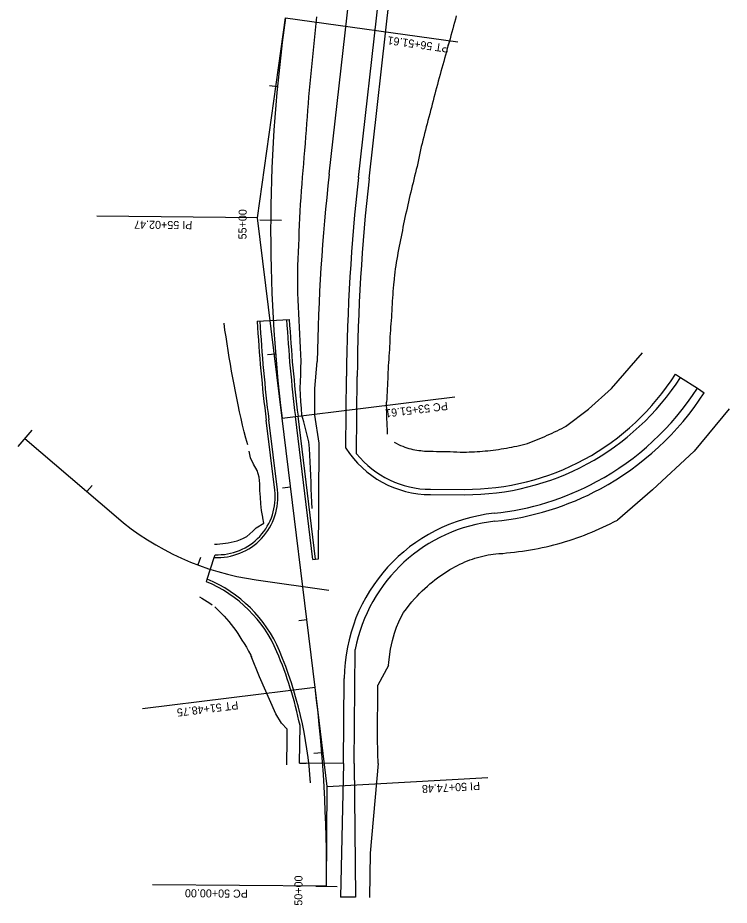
# Model space of a CAD drawing. Extents: x 1304554 to 1314558, y 2088110 to 2090513.
# Drawn here: x 1313759 to 1314290, y 2088110 to 2088773 of the extents above; entities that cross this region are included whole.
import ezdxf

# ---------------------------------------------------------------- set-up
doc = ezdxf.new("R2010")
doc.units = 0
for name, color, linetype in [('R_Horz Alg', 7, 'Continuous'), ('R_Horz Alg Annot', 7, 'Continuous'), ('R_Horz Alg Stationing', 7, 'Continuous'), ('R_Horz Alg Stationing_Detour', 7, 'Continuous'), ('R_Proposed Const Limits', 7, 'Continuous'), ('R_Proposed Road', 7, 'Continuous'), ('R_Shoulder', 7, 'Continuous')]:
    doc.layers.add(name, color=color, linetype=linetype)

msp = doc.modelspace()

# ---------------------------------------------------------------- linework, layer by layer
at = {"layer": 'R_Horz Alg'}
for p, q in [((1313980.75, 2088272.19), (1313956.03, 2088473.54)), ((1313980.75, 2088272.19), (1313956.03, 2088473.54)), ((1313980.75, 2088272.19), (1313956.03, 2088473.54)), ((1313763.74, 2088458.44), (1313831.96, 2088400)), ((1313936.6, 2088352.77), (1313990.95, 2088345.13))]:
    msp.add_line(p, q, dxfattribs=at)
for centre, radius, start, end in [((1315093.4, 2088613.19), 1145.92, 172, 187), ((1315093.4, 2088613.19), 1145.92, 172, 187), ((1313965.08, 2088555.41), 204.63, 229.41667, 262), ((1312843.38, 2088132.54), 1145.92, 359.5625, 7), ((1312843.38, 2088132.54), 1145.92, 359.5625, 7)]:
    msp.add_arc(centre, radius, start, end, dxfattribs=at)
at = {"layer": 'R_Horz Alg Annot'}
for points in [[(1313956.03, 2088473.54), (1313937.64, 2088623.28), (1313958.64, 2088772.67)], [(1313958.64, 2088772.67), (1314087.38, 2088754.58)], [(1313937.64, 2088623.28), (1313817.65, 2088624.33)], [(1313956.03, 2088473.54), (1314085.06, 2088489.38)], [(1313980.75, 2088272.19), (1313851.72, 2088256.35)], [(1313989.26, 2088123.79), (1313989.83, 2088198.27), (1313980.75, 2088272.19)], [(1313989.83, 2088198.27), (1314109.63, 2088205.14)], [(1313989.26, 2088123.79), (1313859.26, 2088124.78)]]:
    msp.add_lwpolyline(points, dxfattribs=at)
at = {"layer": 'R_Horz Alg Stationing'}
for points in [[(1313946.64, 2088721.99), (1313952.61, 2088721.42)], [(1313939.52, 2088621.64), (1313955.52, 2088621.52)], [(1313945.17, 2088521.2), (1313951.15, 2088521.68)], [(1313956.36, 2088421.58), (1313962.32, 2088422.31)], [(1313968.55, 2088322.33), (1313974.51, 2088323.06)], [(1313968.55, 2088322.33), (1313974.51, 2088323.06)], [(1313979.68, 2088223.22), (1313985.66, 2088223.69)], [(1313981.26, 2088123.85), (1313997.26, 2088123.73)]]:
    msp.add_lwpolyline(points, dxfattribs=at)
at = {"layer": 'R_Horz Alg Stationing_Detour'}
for points in [[(1313768.94, 2088464.52), (1313758.53, 2088452.37)], [(1313814.03, 2088423.26), (1313810.13, 2088418.71)], [(1313895.09, 2088369.52), (1313892.97, 2088363.91)]]:
    msp.add_lwpolyline(points, dxfattribs=at)
at = {"layer": 'R_Proposed Const Limits'}
msp.add_line((1314035.5, 2088288.69), (1314027.56, 2088274.13), dxfattribs=at)
for points in [[(1314086.21, 2088774.06), (1314085.54, 2088771.62), (1314084.86, 2088769.18), (1314084.19, 2088766.74), (1314083.52, 2088764.3), (1314082.84, 2088761.87), (1314082.16, 2088759.43), (1314081.49, 2088756.99), (1314080.81, 2088754.55), (1314080.14, 2088752.11), (1314079.46, 2088749.67), (1314078.79, 2088747.23), (1314078.11, 2088744.79), (1314077.43, 2088742.35), (1314076.76, 2088739.91), (1314076.08, 2088737.47), (1314075.41, 2088735.03), (1314074.73, 2088732.59), (1314074.03, 2088730.15), (1314073.33, 2088727.72), (1314072.69, 2088725.27), (1314072.04, 2088722.83), (1314071.4, 2088720.39), (1314070.75, 2088717.94), (1314070.12, 2088715.5), (1314069.48, 2088713.06), (1314068.85, 2088710.61), (1314068.22, 2088708.17), (1314067.58, 2088705.72), (1314066.95, 2088703.28), (1314066.31, 2088700.83), (1314065.68, 2088698.39), (1314065.04, 2088695.95), (1314064.41, 2088693.5), (1314063.77, 2088691.06), (1314063.14, 2088688.61), (1314062.51, 2088686.17), (1314061.87, 2088683.72), (1314061.24, 2088681.28), (1314060.6, 2088678.84), (1314060.05, 2088676.38), (1314059.55, 2088673.92), (1314059.05, 2088671.46), (1314058.55, 2088669), (1314058.05, 2088666.54), (1314057.5, 2088664.09), (1314056.87, 2088661.65), (1314056.24, 2088659.2), (1314055.62, 2088656.75), (1314055.04, 2088654.3), (1314054.45, 2088651.85), (1314053.87, 2088649.4), (1314053.3, 2088647.02), (1314052.74, 2088644.66), (1314052.18, 2088642.29), (1314051.59, 2088639.93), (1314051.01, 2088637.57), (1314050.45, 2088635.21), (1314049.92, 2088632.84), (1314049.4, 2088630.47), (1314048.88, 2088628.09), (1314048.36, 2088625.72), (1314047.86, 2088623.34), (1314047.35, 2088620.97), (1314046.86, 2088618.59), (1314046.36, 2088616.21), (1314045.88, 2088613.83), (1314045.4, 2088611.44), (1314044.92, 2088609.06), (1314044.45, 2088606.67), (1314043.99, 2088604.28), (1314043.53, 2088601.9), (1314043.08, 2088599.51), (1314042.63, 2088597.11), (1314042.22, 2088594.72), (1314041.78, 2088592.33), (1314041.34, 2088589.93), (1314040.9, 2088587.53), (1314040.58, 2088585.13), (1314040.31, 2088582.72), (1314040.04, 2088580.31), (1314039.78, 2088577.9), (1314039.7, 2088577.16), (1314039.54, 2088575.49), (1314039.31, 2088573.08), (1314039.09, 2088570.67), (1314038.87, 2088568.25), (1314038.68, 2088565.84), (1314038.52, 2088563.42), (1314038.37, 2088561), (1314038.22, 2088558.59), (1314038.08, 2088556.17), (1314037.94, 2088553.75), (1314037.8, 2088551.33), (1314037.67, 2088548.91), (1314037.49, 2088546.49), (1314037.3, 2088544.08), (1314037.12, 2088541.66), (1314036.94, 2088539.24), (1314036.76, 2088536.82), (1314036.64, 2088534.4), (1314036.52, 2088531.98), (1314036.41, 2088529.56), (1314036.31, 2088527.14), (1314036.18, 2088524.72), (1314036.02, 2088522.29), (1314035.86, 2088519.87), (1314035.71, 2088517.45), (1314035.56, 2088515.03), (1314035.41, 2088512.61), (1314035.27, 2088510.18), (1314035.15, 2088507.76), (1314035.07, 2088505.33), (1314035, 2088502.86), (1314034.87, 2088500.36), (1314034.73, 2088497.86), (1314034.6, 2088495.36), (1314034.46, 2088492.86), (1314034.33, 2088490.36), (1314034.2, 2088487.86), (1314034.07, 2088485.36)], [(1313978.43, 2088406.02), (1313978.26, 2088410.79), (1313978.07, 2088415.79), (1313977.88, 2088420.79), (1313977.68, 2088425.79), (1313977.46, 2088430.8), (1313977.22, 2088435.8), (1313976.97, 2088440.8), (1313976.74, 2088445.8), (1313976.52, 2088450.8), (1313976.1, 2088455.81), (1313974.82, 2088460.82), (1313973.59, 2088465.83), (1313972.34, 2088470.84), (1313970.83, 2088475.85), (1313970.48, 2088480.85), (1313970.14, 2088485.85), (1313969.8, 2088490.86), (1313969.45, 2088495.86), (1313969.69, 2088500.86), (1313969.93, 2088505.87), (1313970.16, 2088510.94), (1313970.4, 2088516.02), (1313970.09, 2088521.1), (1313969.8, 2088526.18), (1313969.53, 2088531.27), (1313969.24, 2088536.36), (1313968.97, 2088541.46), (1313968.71, 2088546.55), (1313968.47, 2088551.65), (1313968.25, 2088556.75), (1313968.06, 2088561.86), (1313967.89, 2088566.96), (1313967.74, 2088572.07), (1313967.69, 2088577.17), (1313967.68, 2088582.27), (1313967.84, 2088587.37), (1313968.01, 2088592.46), (1313968.21, 2088597.56), (1313968.44, 2088602.65), (1313968.67, 2088607.75), (1313968.9, 2088612.84), (1313969.12, 2088617.94), (1313969.35, 2088623.04), (1313969.6, 2088628.14), (1313969.87, 2088633.23), (1313970.19, 2088638.33), (1313970.57, 2088643.42), (1313970.97, 2088648.5), (1313971.38, 2088653.59), (1313971.81, 2088658.66), (1313972.23, 2088663.65), (1313972.65, 2088668.63), (1313973.08, 2088673.61), (1313973.46, 2088678.6), (1313973.84, 2088683.59), (1313974.2, 2088688.58), (1313974.58, 2088693.57), (1313974.96, 2088698.56), (1313975.33, 2088703.55), (1313975.7, 2088708.54), (1313976.07, 2088713.53), (1313976.51, 2088718.51), (1313976.99, 2088723.49), (1313977.48, 2088728.47), (1313977.96, 2088733.45), (1313978.44, 2088738.42), (1313978.93, 2088743.4), (1313979.41, 2088748.38), (1313979.89, 2088753.35), (1313980.38, 2088758.33), (1313980.88, 2088763.31), (1313981.46, 2088768.27), (1313982.06, 2088773.24)], [(1313930.55, 2088453.68), (1313928.84, 2088458.5), (1313927.63, 2088463.39), (1313926.75, 2088467.2), (1313926.5, 2088468.29), (1313925.37, 2088473.28), (1313924.24, 2088478.32), (1313923.14, 2088483.36), (1313922.12, 2088488.42), (1313921.13, 2088493.49), (1313920.16, 2088498.56), (1313919.2, 2088503.63), (1313918.28, 2088508.72), (1313917.39, 2088513.81), (1313916.5, 2088518.9), (1313915.66, 2088524.01), (1313914.92, 2088529.12), (1313914.15, 2088534.23), (1313913.37, 2088539.35), (1313912.69, 2088544.48)], [(1314167.68, 2088467.3), (1314185.05, 2088480.27), (1314202.04, 2088495.78), (1314225.41, 2088522.31)], [(1314034.89, 2088461.56), (1314034.8, 2088462.86), (1314034.69, 2088465.36), (1314034.58, 2088467.86), (1314034.47, 2088470.36), (1314034.36, 2088472.86), (1314034.28, 2088475.36), (1314034.27, 2088477.86), (1314034.24, 2088480.36), (1314034.12, 2088482.86), (1314034.07, 2088485.36)], [(1314290.13, 2088480.41), (1314264.03, 2088448.82), (1314232.76, 2088419.88), (1314206.53, 2088397.34)], [(1314039.74, 2088455.67), (1314041.35, 2088454.73), (1314042.97, 2088453.93), (1314044.56, 2088453.2), (1314046.13, 2088452.55), (1314047.69, 2088451.97), (1314049.22, 2088451.45), (1314050.74, 2088450.98), (1314052.25, 2088450.58), (1314053.74, 2088450.23), (1314055.23, 2088449.93), (1314056.7, 2088449.69), (1314058.15, 2088449.45), (1314059.59, 2088449.26), (1314061.03, 2088449.12), (1314062.46, 2088448.98), (1314063.88, 2088448.88), (1314065.3, 2088448.81), (1314066.72, 2088448.8), (1314069.02, 2088448.76), (1314071.52, 2088448.7), (1314074.02, 2088448.64), (1314076.52, 2088448.67), (1314079.02, 2088448.59), (1314081.52, 2088448.5), (1314084.02, 2088448.41), (1314086.52, 2088448.32), (1314089.02, 2088448.22), (1314091.52, 2088448.16), (1314093.74, 2088448.19), (1314095.74, 2088448.25), (1314097.75, 2088448.33), (1314099.75, 2088448.42), (1314101.75, 2088448.53), (1314103.75, 2088448.67), (1314105.75, 2088448.82), (1314107.75, 2088448.99), (1314109.74, 2088449.18), (1314111.74, 2088449.39), (1314113.73, 2088449.63), (1314115.71, 2088449.92), (1314117.7, 2088450.22), (1314119.68, 2088450.54), (1314121.66, 2088450.85), (1314123.63, 2088451.19), (1314125.61, 2088451.54), (1314127.58, 2088451.91), (1314129.55, 2088452.3), (1314131.52, 2088452.71), (1314133.49, 2088453.13), (1314135.45, 2088453.58), (1314137.4, 2088454.07), (1314139.31, 2088454.7), (1314141.2, 2088455.38), (1314143.08, 2088456.09), (1314144.96, 2088456.81), (1314146.82, 2088457.56), (1314148.68, 2088458.32), (1314150.53, 2088459.09), (1314152.37, 2088459.89), (1314154.2, 2088460.7), (1314156.02, 2088461.54), (1314157.85, 2088462.36), (1314159.67, 2088463.2), (1314161.48, 2088464.05), (1314163.27, 2088464.94), (1314165.04, 2088465.87), (1314166.81, 2088466.82), (1314168.56, 2088467.78)], [(1313938.89, 2088429.51), (1313937.35, 2088434.36), (1313934.56, 2088439.06), (1313932.4, 2088443.83), (1313931.47, 2088448.75)], [(1313942.43, 2088395.18), (1313941.7, 2088399.07), (1313941.6, 2088399.62), (1313940.69, 2088404.55), (1313940.1, 2088409.51), (1313939.79, 2088414.51), (1313939.48, 2088419.51), (1313939.31, 2088424.53), (1313938.89, 2088429.51)], [(1314046.85, 2088328.27), (1314048.89, 2088331.11), (1314050.91, 2088333.74), (1314052.91, 2088336.18), (1314054.88, 2088338.47), (1314056.85, 2088340.6), (1314058.81, 2088342.61), (1314060.74, 2088344.52), (1314062.66, 2088346.33), (1314064.57, 2088348.05), (1314066.46, 2088349.68), (1314068.35, 2088351.24), (1314070.23, 2088352.73), (1314072.09, 2088354.16), (1314073.96, 2088355.52), (1314075.83, 2088356.82), (1314077.69, 2088358.06), (1314079.55, 2088359.24), (1314081.41, 2088360.37), (1314083.28, 2088361.44), (1314085.14, 2088362.46), (1314087.01, 2088363.43), (1314088.87, 2088364.35), (1314090.74, 2088365.24), (1314092.61, 2088366.07), (1314094.48, 2088366.85), (1314096.36, 2088367.57), (1314098.24, 2088368.25), (1314100.13, 2088368.88), (1314102.07, 2088369.48), (1314104.05, 2088370.03), (1314106.02, 2088370.53), (1314107.98, 2088370.98), (1314109.94, 2088371.36), (1314111.9, 2088371.68), (1314113.86, 2088371.94), (1314115.82, 2088372.15), (1314117.88, 2088372.31), (1314120.85, 2088372.53), (1314123.82, 2088372.8), (1314126.78, 2088373.11), (1314129.74, 2088373.46), (1314132.7, 2088373.82), (1314135.66, 2088374.23), (1314138.61, 2088374.67), (1314141.56, 2088375.15), (1314144.5, 2088375.69), (1314147.43, 2088376.25), (1314150.37, 2088376.84), (1314153.29, 2088377.47), (1314156.21, 2088378.14), (1314159.12, 2088378.85), (1314162.01, 2088379.64), (1314164.88, 2088380.47), (1314167.75, 2088381.33), (1314170.61, 2088382.24), (1314173.46, 2088383.17), (1314176.29, 2088384.15), (1314179.12, 2088385.16), (1314181.92, 2088386.21), (1314184.72, 2088387.3), (1314187.5, 2088388.42), (1314190.27, 2088389.58), (1314193.02, 2088390.78), (1314195.75, 2088392.02), (1314198.47, 2088393.3), (1314201.17, 2088394.61), (1314203.86, 2088395.95), (1314206.53, 2088397.34)], [(1313905.58, 2088379.49), (1313907.58, 2088379.5), (1313909.6, 2088379.59), (1313911.65, 2088379.76), (1313913.73, 2088380.02), (1313915.85, 2088380.36), (1313918.04, 2088380.77), (1313920.27, 2088381.29), (1313922.55, 2088381.98), (1313924.88, 2088382.84), (1313927.29, 2088383.86), (1313929.68, 2088385.22), (1313931.92, 2088387.07), (1313934.24, 2088389.15), (1313936.68, 2088391.59), (1313942.43, 2088395.18)], [(1313894.21, 2088340.03), (1313896.18, 2088338.95), (1313898.14, 2088337.82), (1313900.07, 2088336.61), (1313901.99, 2088335.35), (1313903.89, 2088334.01)], [(1313905.7, 2088332.47), (1313907.49, 2088330.86), (1313909.25, 2088329.15), (1313911, 2088327.36), (1313912.77, 2088325.52), (1313914.53, 2088323.58), (1313916.3, 2088321.54), (1313918.07, 2088319.38), (1313919.84, 2088317.07), (1313921.41, 2088314.86), (1313922.95, 2088312.56), (1313924.47, 2088310.15), (1313925.98, 2088307.63), (1313927.68, 2088305.1), (1313929.37, 2088302.4), (1313931.04, 2088299.5), (1313932.7, 2088296.34), (1313933.28, 2088295.16)], [(1314035.5, 2088288.69), (1314035.67, 2088291.28), (1314037.07, 2088300.9), (1314038.48, 2088307.51), (1314040.04, 2088312.83), (1314041.58, 2088317.41), (1314043.25, 2088321.43), (1314044.97, 2088325.05), (1314046.85, 2088328.27)], [(1313955.58, 2088245.76), (1313951.26, 2088252.58), (1313939.22, 2088280.17), (1313932.99, 2088295.75)], [(1314027.83, 2088215.4), (1314027.75, 2088217.9), (1314027.67, 2088220.41), (1314027.6, 2088222.91), (1314027.53, 2088225.41), (1314027.45, 2088227.91), (1314027.38, 2088230.41), (1314027.35, 2088232.91), (1314027.32, 2088235.41), (1314027.29, 2088237.91), (1314027.27, 2088240.41), (1314027.3, 2088242.91), (1314027.33, 2088245.41), (1314027.36, 2088247.91), (1314027.4, 2088250.41), (1314027.43, 2088252.91), (1314027.47, 2088255.41), (1314027.49, 2088257.91), (1314027.49, 2088260.41), (1314027.5, 2088262.91), (1314027.5, 2088265.41), (1314027.51, 2088267.91), (1314027.52, 2088270.41), (1314027.56, 2088274.13)], [(1313959.57, 2088214.44), (1313959.58, 2088216.71), (1313959.65, 2088221.62), (1313959.71, 2088226.53), (1313959.77, 2088231.44), (1313959.82, 2088236.36), (1313959.87, 2088241.28), (1313955.58, 2088245.76)], [(1314027.83, 2088215.4), (1314021.86, 2088148.65), (1314021.38, 2088115.45)]]:
    msp.add_lwpolyline(points, dxfattribs=at)
at = {"layer": 'R_Proposed Road'}
for p, q in [((1313991.22, 2088655.7), (1314042.63, 2089111.32)), ((1314013.09, 2088653.23), (1314064.49, 2089108.85)), ((1313937.44, 2088545.92), (1313961.4, 2088547.32)), ((1313980.6, 2088495.77), (1313982.3, 2088515.84)), ((1314003.76, 2088451.16), (1314004.17, 2088504.83)), ((1314253.73, 2088503.98), (1314266.32, 2088495.83)), ((1313980.45, 2088475.77), (1313980.6, 2088495.77)), ((1313983.79, 2088454.75), (1313980.45, 2088475.77)), ((1313952.54, 2088419.93), (1313946.1, 2088472.32)), ((1313979.07, 2088367.95), (1313965.96, 2088474.76)), ((1313983.13, 2088368.45), (1313983.79, 2088454.75)), ((1314066.92, 2088416.38), (1314092.53, 2088416.32)), ((1313900.05, 2088353.27), (1313905.28, 2088369.52)), ((1313979.07, 2088367.95), (1313983.13, 2088368.45)), ((1314001.96, 2088215.6), (1314002.45, 2088279.08)), ((1314001.96, 2088215.6), (1313973.91, 2088215.82)), ((1314001.96, 2088215.6), (1313999.62, 2088115.62))]:
    msp.add_line(p, q, dxfattribs=at)
for centre, radius, start, end in [((1315424.52, 2088493.98), 1442.39, 173.5625, 179.13177), ((1315424.52, 2088493.98), 1420.39, 173.5625, 179.5625), ((1315093.4, 2088613.19), 1155.92, 183.33052, 187), ((1315093.4, 2088613.19), 1135.92, 183.33052, 187), ((1314092.56, 2088607.92), 191.79, 298.44752, 327.19752), ((1314092.56, 2088607.92), 206.79, 298.43857, 327.18857), ((1314067.07, 2088491.38), 75, 212.42238, 269.88333), ((1314092.92, 2088608.11), 191.79, 269.88333, 298.3245), ((1314092.92, 2088608.11), 206.79, 275.97277, 298.3245), ((1313907.87, 2088414.45), 45, 266.69941, 7), ((1314127.44, 2088278.12), 125, 95.97277, 179.5625), ((1313861.94, 2088260.82), 100, 22.92448, 67.5945), ((1313677.73, 2088182.91), 300, 3.45495, 22.92448)]:
    msp.add_arc(centre, radius, start, end, dxfattribs=at)
at = {"layer": 'R_Shoulder'}
for p, q in [((1314021.03, 2088652.34), (1314072.44, 2089107.95)), ((1314011.73, 2088446.9), (1314012.17, 2088504.76)), ((1314250.01, 2088506.39), (1314253.73, 2088503.98)), ((1314266.33, 2088495.82), (1314271.49, 2088492.48)), ((1313950.55, 2088419.69), (1313944.12, 2088472.08)), ((1313981.06, 2088368.19), (1313967.94, 2088475)), ((1314066.93, 2088420.38), (1314092.54, 2088420.32)), ((1313905.28, 2088369.52), (1313905.92, 2088371.49)), ((1313899.44, 2088351.36), (1313900, 2088353.11)), ((1314009.96, 2088215.54), (1314010.61, 2088300.74)), ((1313969.16, 2088215.85), (1313973.91, 2088215.82)), ((1314009.96, 2088215.54), (1314010.82, 2088115.53)), ((1314010.82, 2088115.53), (1313999.62, 2088115.62))]:
    msp.add_line(p, q, dxfattribs=at)
msp.add_lwpolyline([(1313969.16, 2088215.85), (1313969.42, 2088243.92)], dxfattribs=at)
for centre, radius, start, end in [((1315424.52, 2088493.98), 1412.39, 173.5625, 179.5625), ((1315093.4, 2088613.19), 1157.92, 183.33052, 187), ((1315093.4, 2088613.19), 1133.92, 183.33052, 187), ((1314091.75, 2088607.48), 187.79, 298.73164, 327.43214), ((1314092.84, 2088608.07), 212.79, 298.34924, 327.09619), ((1314067.07, 2088491.38), 71, 218.78938, 269.88333), ((1314092.92, 2088608.11), 187.79, 269.88333, 298.3245), ((1313907.87, 2088414.45), 43, 267.39133, 7), ((1314092.92, 2088608.11), 212.79, 275.97277, 298.3245), ((1314127.44, 2088278.12), 119, 95.97277, 169.04314), ((1313861.94, 2088260.82), 98, 22.92448, 67.50099), ((1313677.73, 2088182.91), 298, 11.8124, 22.92448)]:
    msp.add_arc(centre, radius, start, end, dxfattribs=at)

# ---------------------------------------------------------------- texts
at = {"layer": 'R_Horz Alg Annot'}
for s, rotation, p in [('PT 56+51.61', 172, (1314081.02, 2088752.44)), ('PI 55+02.47', 179.5, (1313889.02, 2088620.7)), ('PC 53+51.61', 187, (1314079.47, 2088485.67)), ('PT 51+48.75', 187, (1313922.93, 2088262.07)), ('PI 50+74.48', 183.28125, (1314103.81, 2088201.8)), ('PC 50+00.00', 179.5625, (1313930.53, 2088121.24))]:
    msp.add_text(s, height=6, rotation=rotation, dxfattribs=at).set_placement(p)
at = {"layer": 'R_Horz Alg Stationing'}
for s, rotation, p in [('55+00', 89.58052, (1313929.41, 2088607.07)), ('50+00', 89.5625, (1313971.15, 2088109.28))]:
    msp.add_text(s, height=6, rotation=rotation, dxfattribs=at).set_placement(p)

doc.saveas('drawing.dxf')
